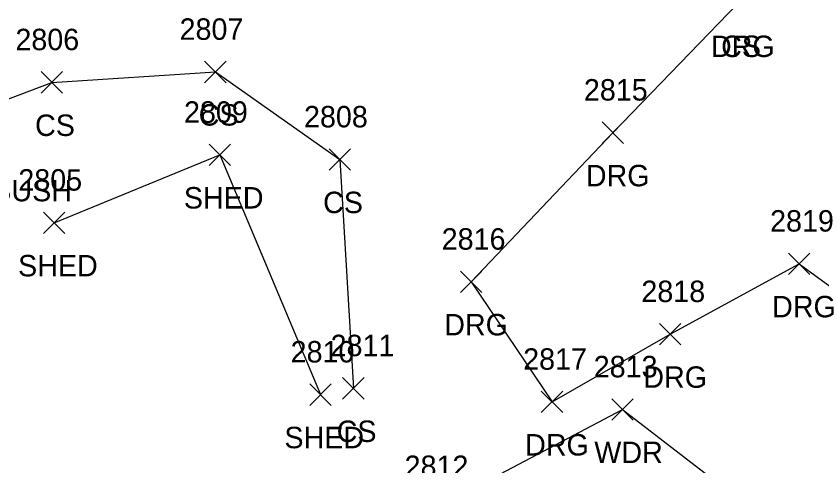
# Model space of a CAD drawing. Extents: x 1499292 to 1501024, y 534584 to 538043.
# Drawn here: x 1499593.1 to 1499668.2, y 537697.5 to 537739.4 of the extents above; entities that cross this region are included whole.
import ezdxf

# ---------------------------------------------------------------- set-up
doc = ezdxf.new("R2010")
doc.units = 0
for name, color, linetype in [('L_A', 7, 'Continuous'), ('L_C', 7, 'Continuous'), ('L_I', 7, 'Continuous'), ('L_TIC', 7, 'Continuous'), ('LAWA', 7, 'Continuous'), ('LBC', 7, 'Continuous'), ('LELB', 7, 'Continuous'), ('R_A', 7, 'Continuous'), ('R_I', 7, 'Continuous'), ('R_TIC', 7, 'Continuous'), ('RDG', 7, 'Continuous')]:
    doc.layers.add(name, color=color, linetype=linetype)

msp = doc.modelspace()

# ---------------------------------------------------------------- linework, layer by layer
at = {"layer": 'L_TIC'}
for points in [[(1499610.665, 537733.236), (1499612.665, 537735.236)], [(1499612.665, 537733.236), (1499610.665, 537735.236)], [(1499595.409, 537732.268), (1499597.409, 537734.268)], [(1499597.409, 537732.268), (1499595.409, 537734.268)], [(1499611.087, 537725.499), (1499613.087, 537727.499)], [(1499613.087, 537725.499), (1499611.087, 537727.499)], [(1499622.27, 537725.069), (1499624.27, 537727.069)], [(1499624.27, 537725.069), (1499622.27, 537727.069)], [(1499595.627, 537719.169), (1499597.627, 537721.169)], [(1499597.627, 537719.169), (1499595.627, 537721.169)], [(1499623.535, 537703.724), (1499625.535, 537705.724)], [(1499625.535, 537703.724), (1499623.535, 537705.724)], [(1499620.462, 537703.137), (1499622.462, 537705.137)], [(1499622.462, 537703.137), (1499620.462, 537705.137)], [(1499648.641, 537701.753), (1499650.641, 537703.753)], [(1499650.641, 537701.753), (1499648.641, 537703.753)]]:
    msp.add_lwpolyline(points, dxfattribs=at)
at = {"layer": 'LAWA'}
msp.add_lwpolyline([(1499632.006, 537693.454), (1499649.641, 537702.753), (1499663.307, 537692.2)], dxfattribs=at)
at = {"layer": 'LBC'}
msp.add_lwpolyline([(1499596.627, 537720.169), (1499612.087, 537726.499), (1499621.462, 537704.137)], dxfattribs=at)
at = {"layer": 'LELB'}
msp.add_lwpolyline([(1499582.257, 537727.91), (1499596.409, 537733.268), (1499611.665, 537734.236), (1499623.27, 537726.069), (1499624.535, 537704.724)], dxfattribs=at)
at = {"layer": 'R_TIC'}
for points in [[(1499647.725, 537727.571), (1499649.725, 537729.571)], [(1499649.725, 537727.571), (1499647.725, 537729.571)], [(1499665.097, 537715.349), (1499667.097, 537717.349)], [(1499667.097, 537715.349), (1499665.097, 537717.349)], [(1499634.519, 537713.664), (1499636.519, 537715.664)], [(1499636.519, 537713.664), (1499634.519, 537715.664)], [(1499653.084, 537708.775), (1499655.084, 537710.775)], [(1499655.084, 537708.775), (1499653.084, 537710.775)], [(1499642.061, 537702.46), (1499644.061, 537704.46)], [(1499644.061, 537702.46), (1499642.061, 537704.46)]]:
    msp.add_lwpolyline(points, dxfattribs=at)
at = {"layer": 'RDG'}
msp.add_lwpolyline([(1499616.247, 537822.183), (1499611.438, 537814.178), (1499627.998, 537804.719), (1499648.228, 537793.601), (1499657.65, 537787.037), (1499661.233, 537780.563), (1499662.782, 537771.708), (1499664.288, 537756.487), (1499660.39, 537740.632), (1499648.725, 537728.571), (1499635.519, 537714.664), (1499643.061, 537703.46), (1499654.084, 537709.775), (1499666.097, 537716.349), (1499687.017, 537701.096), (1499694.358, 537709.594), (1499686.467, 537716.113), (1499685.219, 537725.482), (1499686.936, 537727.795), (1499688.073, 537727.086)], dxfattribs=at)

# ---------------------------------------------------------------- texts
at = {"layer": 'L_A'}
for s, p in [('CS', (1499658.831, 537735.632)), ('CS', (1499610.106, 537729.236)), ('CS', (1499594.85, 537728.268)), ('SHED', (1499608.724, 537721.499)), ('CS', (1499621.711, 537721.069)), ('SHED', (1499593.265, 537715.169)), ('CS', (1499622.976, 537699.724)), ('SHED', (1499618.1, 537699.137)), ('WDR', (1499647.003, 537697.753))]:
    msp.add_text(s, height=2, dxfattribs=at).set_placement(p)
at = {"layer": 'L_C'}
msp.add_text('BURNING BUSH', height=2, dxfattribs=at).set_placement((1499577.786, 537722.172))
at = {"layer": 'L_I'}
for s, p in [('2807', (1499608.326, 537737.236)), ('2806', (1499593.015, 537736.268)), ('2809', (1499608.74, 537729.499)), ('2808', (1499619.931, 537729.069)), ('2805', (1499593.289, 537723.169)), ('2811', (1499622.409, 537707.724)), ('2810', (1499618.683, 537707.137)), ('2813', (1499646.948, 537705.753)), ('2812', (1499629.313, 537696.454))]:
    msp.add_text(s, height=2, dxfattribs=at).set_placement(p)
at = {"layer": 'R_A'}
for p in [(1499657.878, 537735.632), (1499646.213, 537723.571), (1499663.585, 537711.349), (1499633.008, 537709.664), (1499651.572, 537704.775), (1499640.549, 537698.46)]:
    msp.add_text('DRG', height=2, dxfattribs=at).set_placement(p)
at = {"layer": 'R_I'}
for s, p in [('2815', (1499646.032, 537731.571)), ('2819', (1499663.396, 537719.349)), ('2816', (1499632.771, 537717.664)), ('2818', (1499651.391, 537712.775)), ('2817', (1499640.368, 537706.46))]:
    msp.add_text(s, height=2, dxfattribs=at).set_placement(p)

doc.saveas('drawing.dxf')
